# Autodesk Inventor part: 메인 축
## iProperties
Created: 2014-10
Part Number: 메인 축
Document SubType Name: Modeling
Designer: KYOUNG IL JANG
Density: 1 g/cm^3
Mass: 29.2926 g
Surface Area: 74.3518 cm^2
Volume: 29.2926 cm^3
Author: SeoGD™ [www.esajin.kr]
Revision Number: 1
